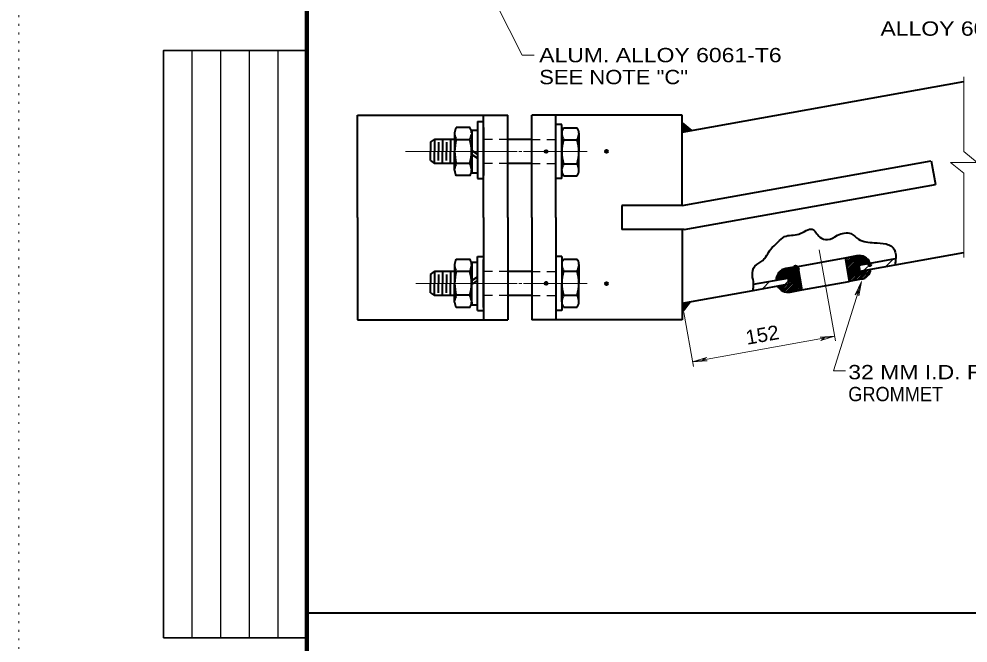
# Model space of a CAD drawing. Extents: x 312583 to 312854, y 144419 to 144597.
# Drawn here: x 312601.2 to 312651.6, y 144456.6 to 144489.8 of the extents above; entities that cross this region are included whole.
import ezdxf

# ---------------------------------------------------------------- set-up
doc = ezdxf.new("R2010")
doc.units = 0
doc.header["$LTSCALE"] = 0.3
doc.header["$PDMODE"] = 32
doc.header["$PDSIZE"] = 0.15
doc.linetypes.add('DOTTED', pattern=[1.5, 0.3, -1.2])
doc.linetypes.add('SHORT_DASHED', pattern=[2.7, 1.5, -1.2])
for name, color, linetype, lineweight in [('1', 7, 'Continuous', 40), ('2', 7, 'Continuous', 40), ('62', 7, 'DOTTED', 13)]:
    doc.layers.add(name, color=color, linetype=linetype, lineweight=lineweight)

msp = doc.modelspace()

# ---------------------------------------------------------------- linework, layer by layer
at = {"layer": '1', "lineweight": 13}
for p, q in [((312626.547, 144490.596), (312627.9347, 144487.8743)), ((312627.9347, 144487.8743), (312628.571, 144487.8743)), ((312651.3947, 144486.7166), (312651.3947, 144482.7453)), ((312627.6663, 144482.753), (312621.74, 144482.753)), ((312627.7583, 144482.753), (312627.9117, 144482.753)), ((312628.0113, 144482.753), (312631.3847, 144482.753)), ((312651.3947, 144481.603), (312651.3947, 144477.118)), ((312643.7127, 144477.5166), (312644.579, 144472.679)), ((312646.0893, 144476.4203), (312646.4957, 144476.819)), ((312647.2623, 144476.6273), (312647.6687, 144477.0336)), ((312627.6663, 144475.7226), (312622.2767, 144475.7226)), ((312627.7583, 144475.7226), (312627.9117, 144475.7226)), ((312628.0113, 144475.7226), (312631.3847, 144475.7226)), ((312640.6997, 144475.4543), (312641.0983, 144475.853)), ((312641.8803, 144475.6613), (312642.072, 144475.853)), ((312645.959, 144475.8376), (312645.6312, 144475.1339)), ((312645.959, 144475.8376), (312645.8169, 144475.0732)), ((312645.6312, 144475.1339), (312645.7974, 144475.3364)), ((312645.8169, 144475.0732), (312645.7974, 144475.3364)), ((312636.5213, 144474.1816), (312637.035, 144471.3143)), ((312636.989, 144471.5673), (312644.533, 144472.932)), ((312644.533, 144472.932), (312643.7587, 144472.886)), ((312643.7587, 144472.886), (312644.0193, 144472.84)), ((312644.533, 144472.932), (312643.797, 144472.702)), ((312643.797, 144472.702), (312644.0193, 144472.84)), ((312636.989, 144471.5673), (312637.7327, 144471.7973)), ((312636.989, 144471.5673), (312637.7633, 144471.6133)), ((312637.7327, 144471.7973), (312637.5027, 144471.6593)), ((312637.7633, 144471.6133), (312637.5027, 144471.6593))]:
    msp.add_line(p, q, dxfattribs=at)
at = {"layer": '1', "lineweight": 25}
for p, q in [((312610.4087, 144456.901), (312610.4087, 144488.1192)), ((312611.9315, 144456.901), (312611.9315, 144488.1192)), ((312613.4543, 144456.901), (312613.4543, 144488.1192)), ((312614.9772, 144456.901), (312614.9772, 144488.1192)), ((312636.4293, 144484.2096), (312636.46, 144484.2403)), ((312636.4293, 144484.1253), (312636.506, 144484.202)), ((312636.4293, 144484.041), (312636.552, 144484.1636)), ((312636.4293, 144483.9566), (312636.598, 144484.1253)), ((312636.4293, 144483.8723), (312636.644, 144484.087)), ((312636.4293, 144483.788), (312636.69, 144484.0486)), ((312636.5137, 144483.788), (312636.736, 144484.018)), ((312636.6133, 144483.8033), (312636.782, 144483.9796)), ((312636.713, 144483.8263), (312636.828, 144483.9413)), ((312636.8127, 144483.8416), (312636.874, 144483.903)), ((312636.4293, 144474.3963), (312636.782, 144474.749)), ((312636.4293, 144474.4806), (312636.6823, 144474.7336)), ((312636.4293, 144474.565), (312636.5827, 144474.7106)), ((312636.4293, 144474.6416), (312636.483, 144474.6953)), ((312636.4293, 144474.312), (312636.7743, 144474.657)), ((312636.4293, 144474.2276), (312636.506, 144474.3043))]:
    msp.add_line(p, q, dxfattribs=at)
at = {"layer": '1'}
for p, q in [((312636.4293, 144483.7726), (312651.3947, 144486.4636)), ((312619.1793, 144479.2416), (312619.1793, 144484.6696)), ((312625.8877, 144479.2416), (312625.8877, 144484.6696)), ((312627.168, 144479.2416), (312627.168, 144484.6696)), ((312628.4407, 144479.2416), (312628.4407, 144484.6696)), ((312629.721, 144479.2416), (312629.721, 144484.6696)), ((312636.4293, 144479.878), (312636.4293, 144484.6696)), ((312625.5657, 144484.34), (312625.5657, 144481.304)), ((312625.5657, 144484.34), (312625.8877, 144484.34)), ((312630.043, 144484.179), (312629.721, 144484.179)), ((312630.043, 144481.304), (312630.043, 144484.179)), ((312636.4293, 144484.2633), (312636.9277, 144483.8646)), ((312624.339, 144483.7343), (312624.339, 144482.753)), ((312625.167, 144484.018), (312624.431, 144484.018)), ((312625.2513, 144483.742), (312625.2513, 144483.8876)), ((312625.2513, 144483.8876), (312625.2513, 144481.6183)), ((312625.2513, 144483.8876), (312625.5657, 144483.8876)), ((312625.2513, 144483.742), (312625.2513, 144482.753)), ((312625.8877, 144484.018), (312625.8877, 144481.465)), ((312629.721, 144481.465), (312629.721, 144484.018)), ((312630.043, 144483.7266), (312630.043, 144482.7453)), ((312630.1273, 144484.0103), (312630.8557, 144484.0103)), ((312630.9477, 144483.7266), (312630.9477, 144482.7376)), ((312623.0587, 144483.2436), (312623.0587, 144482.7453)), ((312624.339, 144483.3893), (312623.2733, 144483.3893)), ((312623.488, 144483.2436), (312623.488, 144482.7453)), ((312623.7027, 144483.3893), (312623.7027, 144482.7453)), ((312623.9173, 144483.2436), (312623.9173, 144482.7453)), ((312624.132, 144483.3893), (312624.132, 144482.7453)), ((312625.167, 144483.374), (312624.431, 144483.374)), ((312628.4407, 144483.3893), (312627.168, 144483.3893)), ((312630.1273, 144483.3586), (312630.8557, 144483.3586)), ((312623.0587, 144482.2623), (312623.0587, 144482.7606)), ((312623.488, 144482.2623), (312623.488, 144482.7606)), ((312623.7027, 144482.1166), (312623.7027, 144482.7606)), ((312623.9173, 144482.2623), (312623.9173, 144482.7606)), ((312624.132, 144482.1166), (312624.132, 144482.7606)), ((312624.339, 144481.7486), (312624.339, 144482.7606)), ((312625.2513, 144482.8066), (312625.5657, 144482.5996)), ((312625.2513, 144481.741), (312625.2513, 144482.753)), ((312630.043, 144481.7333), (312630.043, 144482.7453)), ((312630.9477, 144481.7333), (312630.9477, 144482.7453)), ((312624.339, 144482.1166), (312623.2733, 144482.1166)), ((312625.2513, 144482.592), (312625.5657, 144482.385)), ((312628.4407, 144482.1166), (312627.168, 144482.1166)), ((312636.4293, 144479.878), (312649.6697, 144482.2546)), ((312649.6697, 144482.2546), (312649.8997, 144480.9973)), ((312625.1593, 144482.1013), (312624.431, 144482.1013)), ((312625.2513, 144481.6183), (312625.2513, 144481.741)), ((312625.2513, 144481.6183), (312625.5657, 144481.6183)), ((312630.1273, 144482.0936), (312630.8557, 144482.0936)), ((312625.167, 144481.465), (312624.431, 144481.465)), ((312625.5657, 144481.304), (312625.8877, 144481.304)), ((312630.043, 144481.304), (312629.721, 144481.304)), ((312630.1273, 144481.4496), (312630.8557, 144481.4496)), ((312636.5367, 144478.5976), (312649.8997, 144480.9973)), ((312636.4293, 144479.878), (312633.2323, 144479.878)), ((312633.2323, 144479.878), (312633.2323, 144478.5976)), ((312619.1793, 144479.2416), (312619.1793, 144473.806)), ((312625.8877, 144479.2416), (312625.8877, 144473.806)), ((312627.168, 144479.2416), (312627.168, 144473.806)), ((312628.4407, 144479.2416), (312628.4407, 144473.806)), ((312629.721, 144479.2416), (312629.721, 144473.806)), ((312636.5367, 144478.5976), (312633.2323, 144478.5976)), ((312636.4293, 144478.5976), (312636.4293, 144473.806)), ((312625.5657, 144474.2966), (312625.5657, 144477.1716)), ((312625.5657, 144477.1716), (312625.8877, 144477.1716)), ((312630.043, 144477.1716), (312629.721, 144477.1716)), ((312630.043, 144477.1716), (312630.043, 144474.2966)), ((312642.578, 144476.6426), (312645.0927, 144477.095)), ((312645.0927, 144477.095), (312645.7213, 144477.21)), ((312645.0927, 144477.095), (312645.315, 144475.8376)), ((312647.7453, 144476.7193), (312651.3947, 144477.3786)), ((312624.339, 144476.7346), (312624.339, 144475.7226)), ((312625.167, 144477.0106), (312624.431, 144477.0106)), ((312625.2513, 144476.865), (312625.2513, 144476.7346)), ((312625.2513, 144476.865), (312625.5657, 144476.865)), ((312625.2513, 144474.588), (312625.2513, 144476.865)), ((312625.2513, 144476.7346), (312625.2513, 144475.7226)), ((312625.8877, 144474.4576), (312625.8877, 144477.0106)), ((312629.721, 144477.0106), (312629.721, 144474.4576)), ((312630.043, 144476.75), (312630.043, 144475.738)), ((312630.1273, 144477.026), (312630.8557, 144477.026)), ((312630.9477, 144476.7423), (312630.9477, 144475.7303)), ((312642.5703, 144476.6426), (312641.9493, 144476.5276)), ((312642.578, 144476.6426), (312642.8003, 144475.3853)), ((312645.8133, 144476.6963), (312646.4267, 144476.8113)), ((312645.8133, 144476.6963), (312645.867, 144476.382)), ((312645.867, 144476.382), (312647.7453, 144476.7193)), ((312646.4267, 144476.8113), (312647.776, 144477.0566)), ((312623.0587, 144476.2133), (312623.0587, 144475.7226)), ((312624.339, 144476.3666), (312623.2733, 144476.3666)), ((312623.488, 144476.2133), (312623.488, 144475.7226)), ((312623.7027, 144476.3666), (312623.7027, 144475.7226)), ((312623.9173, 144476.2133), (312623.9173, 144475.7226)), ((312624.132, 144476.3666), (312624.132, 144475.7226)), ((312625.1593, 144476.3743), (312624.431, 144476.3743)), ((312625.2513, 144475.8836), (312625.5657, 144476.0906)), ((312628.4407, 144476.3666), (312627.168, 144476.3666)), ((312630.1273, 144476.3896), (312630.8557, 144476.3896)), ((312623.0587, 144475.2396), (312623.0587, 144475.7303)), ((312623.488, 144475.2396), (312623.488, 144475.7303)), ((312623.7027, 144475.0863), (312623.7027, 144475.7303)), ((312623.9173, 144475.2396), (312623.9173, 144475.7303)), ((312624.132, 144475.0863), (312624.132, 144475.7303)), ((312624.339, 144474.7413), (312624.339, 144475.7303)), ((312625.2513, 144475.669), (312625.5657, 144475.8836)), ((312625.2513, 144474.7336), (312625.2513, 144475.7226)), ((312630.043, 144474.749), (312630.043, 144475.738)), ((312630.9477, 144474.7566), (312630.9477, 144475.738)), ((312640.2013, 144475.3623), (312642.095, 144475.7073)), ((312640.232, 144475.6996), (312642.0413, 144476.0216)), ((312642.0413, 144476.0216), (312642.095, 144475.7073)), ((312642.8003, 144475.3853), (312645.315, 144475.8376)), ((312645.9437, 144475.9526), (312645.315, 144475.8376)), ((312624.339, 144475.0863), (312623.2733, 144475.0863)), ((312625.167, 144475.1016), (312624.431, 144475.1016)), ((312628.4407, 144475.0863), (312627.168, 144475.0863)), ((312630.1273, 144475.117), (312630.8557, 144475.117)), ((312636.4293, 144474.6876), (312640.2013, 144475.3623)), ((312642.1717, 144475.278), (312642.8003, 144475.3853)), ((312625.2513, 144474.7336), (312625.2513, 144474.588)), ((312625.2513, 144474.588), (312625.5657, 144474.588)), ((312636.4293, 144474.2046), (312636.8587, 144474.7643)), ((312625.167, 144474.4576), (312624.431, 144474.4576)), ((312625.5657, 144474.2966), (312625.8877, 144474.2966)), ((312630.043, 144474.2966), (312629.721, 144474.2966)), ((312630.1273, 144474.473), (312630.8557, 144474.473))]:
    msp.add_line(p, q, dxfattribs=at)
at = {"layer": '1', "linetype": 'SHORT_DASHED', "lineweight": 25}
for p, q in [((312627.168, 144483.3893), (312625.8877, 144483.3893)), ((312628.4407, 144483.3893), (312629.721, 144483.3893)), ((312627.168, 144482.1166), (312625.8877, 144482.1166)), ((312628.4407, 144482.1166), (312629.721, 144482.1166)), ((312627.168, 144476.3666), (312625.8877, 144476.3666)), ((312628.4407, 144476.3666), (312629.721, 144476.3666)), ((312627.168, 144475.0863), (312625.8877, 144475.0863)), ((312628.4407, 144475.0863), (312629.721, 144475.0863))]:
    msp.add_line(p, q, dxfattribs=at)
at = {"layer": '1', "lineweight": 35}
for p, q in [((312645.1003, 144477.049), (312645.154, 144477.1026)), ((312645.108, 144476.98), (312645.2613, 144477.1256)), ((312645.1233, 144476.9033), (312645.361, 144477.141)), ((312645.1387, 144476.8343), (312645.4607, 144477.1563)), ((312645.1463, 144476.7653), (312645.5603, 144477.1793)), ((312645.1617, 144476.6963), (312645.6677, 144477.1946)), ((312645.177, 144476.6273), (312645.7597, 144477.21)), ((312645.1847, 144476.5583), (312645.844, 144477.2176)), ((312645.2, 144476.4816), (312645.9207, 144477.21)), ((312645.2153, 144476.4126), (312645.9973, 144477.1946)), ((312645.223, 144476.3436), (312646.0587, 144477.1716)), ((312645.2383, 144476.2746), (312646.1123, 144477.1486)), ((312645.2537, 144476.2056), (312646.166, 144477.118)), ((312645.8363, 144476.704), (312646.212, 144477.0796)), ((312641.6043, 144475.945), (312642.2483, 144476.5813)), ((312641.704, 144475.9603), (312642.348, 144476.5966)), ((312641.8113, 144475.9756), (312642.4477, 144476.6196)), ((312641.911, 144475.9986), (312642.5473, 144476.635)), ((312642.0107, 144476.014), (312642.5857, 144476.589)), ((312645.2613, 144476.129), (312645.8133, 144476.681)), ((312645.2767, 144476.06), (312645.8287, 144476.612)), ((312646.1353, 144476.7576), (312646.3423, 144476.9646)), ((312646.235, 144476.773), (312646.373, 144476.911)), ((312646.3423, 144476.796), (312646.4037, 144476.8573)), ((312641.4203, 144475.922), (312642.0413, 144476.543)), ((312641.4357, 144476.0216), (312641.9417, 144476.5276)), ((312641.4663, 144476.1366), (312641.8113, 144476.4816)), ((312641.5047, 144475.922), (312642.141, 144476.566)), ((312641.7577, 144475.347), (312642.647, 144476.2363)), ((312641.8113, 144475.3163), (312642.6547, 144476.1596)), ((312641.8803, 144475.301), (312642.67, 144476.0906)), ((312642.049, 144475.968), (312642.5933, 144476.5123)), ((312642.0643, 144475.899), (312642.6087, 144476.4433)), ((312642.0797, 144475.83), (312642.6163, 144476.3743)), ((312642.0873, 144475.761), (312642.6317, 144476.3053)), ((312645.292, 144475.991), (312645.8363, 144476.543)), ((312645.2997, 144475.922), (312645.8517, 144476.4663)), ((312645.315, 144475.853), (312645.867, 144476.405)), ((312645.407, 144475.8606), (312645.936, 144476.3896)), ((312645.5067, 144475.876), (312646.0433, 144476.4126)), ((312645.6063, 144475.899), (312646.143, 144476.428)), ((312645.7137, 144475.9143), (312646.2427, 144476.4433)), ((312645.8133, 144475.9296), (312646.3423, 144476.4663)), ((312645.913, 144475.9526), (312646.442, 144476.4816)), ((312646.028, 144475.9833), (312646.442, 144476.3896)), ((312646.189, 144476.06), (312646.3653, 144476.2363)), ((312641.5047, 144475.5923), (312641.5123, 144475.6)), ((312641.543, 144475.5463), (312641.612, 144475.6153)), ((312641.5737, 144475.4926), (312641.7193, 144475.6383)), ((312641.612, 144475.4543), (312641.819, 144475.6536)), ((312641.658, 144475.4083), (312641.9187, 144475.6766)), ((312641.704, 144475.3776), (312642.0183, 144475.692)), ((312641.9417, 144475.278), (312642.6853, 144476.0216)), ((312642.0183, 144475.2703), (312642.7007, 144475.9526)), ((312642.095, 144475.2703), (312642.7083, 144475.8836)), ((312642.187, 144475.278), (312642.7237, 144475.8146)), ((312642.2943, 144475.301), (312642.739, 144475.7456)), ((312642.394, 144475.3163), (312642.7467, 144475.669)), ((312642.4937, 144475.3316), (312642.762, 144475.6)), ((312642.5933, 144475.3546), (312642.7773, 144475.531)), ((312642.693, 144475.37), (312642.785, 144475.462)), ((312642.7927, 144475.3853), (312642.8003, 144475.393))]:
    msp.add_line(p, q, dxfattribs=at)
at = {"layer": '1', "lineweight": 158}
msp.add_lwpolyline([(312616.5, 144423.1446), (312616.5, 144585.0846), (312849, 144585.0846)], dxfattribs=at)
at = {"layer": '1', "lineweight": 35}
for points in [[(312616.5, 144456.901), (312608.8858, 144456.901), (312608.8858, 144488.1192), (312616.5, 144488.1192)], [(312645.936, 144476.7193), (312646.258, 144477.049), (312646.2657, 144477.049)], [(312646.0357, 144476.7346), (312646.304, 144477.003), (312646.304, 144477.003)]]:
    msp.add_lwpolyline(points, dxfattribs=at)
at = {"layer": '1'}
for points in [[(312619.1793, 144484.6696), (312625.8877, 144484.6696), (312627.168, 144484.6696)], [(312636.4293, 144484.6696), (312629.721, 144484.6696), (312628.4407, 144484.6696)], [(312623.0587, 144483.2436), (312623.2733, 144483.3893), (312623.2733, 144482.7453)], [(312623.0587, 144482.2623), (312623.2733, 144482.1166), (312623.2733, 144482.7606)], [(312623.0587, 144476.2133), (312623.2733, 144476.3666), (312623.2733, 144475.7226)], [(312623.0587, 144475.2396), (312623.2733, 144475.0863), (312623.2733, 144475.7303)], [(312619.1793, 144473.806), (312625.8877, 144473.806), (312627.168, 144473.806)], [(312636.4293, 144473.806), (312629.721, 144473.806), (312628.4407, 144473.806)]]:
    msp.add_lwpolyline(points, dxfattribs=at)
at = {"layer": '1', "lineweight": 25}
msp.add_lwpolyline([(312636.9123, 144483.857), (312636.92, 144483.8646), (312636.92, 144483.8646)], dxfattribs=at)
at = {"layer": '1', "lineweight": 13}
for points in [[(312651.3947, 144481.603), (312650.6893, 144482.1703), (312652.1, 144482.1703), (312651.3947, 144482.7453)], [(312645.959, 144475.8376), (312644.476, 144471.0797), (312645.1123, 144471.0797)]]:
    msp.add_lwpolyline(points, dxfattribs=at)
at = {"layer": '1'}
for centre, radius, start, end in [((312625.8144, 144483.9759), 1.5067, 191.77014, 203.36365), ((312624.8667, 144483.7218), 0.5262, 145.8703, 178.33743), ((312623.7741, 144483.9759), 1.5067, 336.63635, 348.22986), ((312624.7218, 144483.7218), 0.5262, 1.66257, 34.1297), ((312631.5151, 144483.9631), 1.5067, 191.77014, 203.36365), ((312630.5675, 144483.7091), 0.5262, 145.8703, 178.33743), ((312630.4225, 144483.7091), 0.5262, 1.66257, 34.1297), ((312629.4749, 144483.9631), 1.5067, 336.63635, 348.22986), ((312627.0577, 144482.6745), 2.7192, 164.99798, 178.595), ((312622.5308, 144482.6745), 2.7192, 1.405, 15.00202), ((312632.7584, 144482.6618), 2.7192, 164.99798, 178.595), ((312628.2315, 144482.6618), 2.7192, 1.405, 15.00202), ((312627.0577, 144482.8079), 2.7192, 181.405, 195.00202), ((312622.5308, 144482.8079), 2.7192, 344.99798, 358.595), ((312632.7584, 144482.7951), 2.7192, 181.405, 195.00202), ((312628.2315, 144482.7951), 2.7192, 344.99798, 358.595), ((312625.8144, 144481.5065), 1.5067, 156.63635, 168.22986), ((312624.8667, 144481.7606), 0.5262, 181.66257, 214.1297), ((312623.7741, 144481.5065), 1.5067, 11.77014, 23.36365), ((312624.7218, 144481.7606), 0.5262, 325.8703, 358.33743), ((312631.5151, 144481.4937), 1.5067, 156.63635, 168.22986), ((312630.5675, 144481.7478), 0.5262, 181.66257, 214.1297), ((312629.4749, 144481.4937), 1.5067, 11.77014, 23.36365), ((312630.4225, 144481.7478), 0.5262, 325.8703, 358.33743), ((312645.8337, 144476.5817), 0.6361, 20.92751, 100.40744), ((312625.8144, 144476.9717), 1.5067, 191.77014, 203.36365), ((312624.8667, 144476.7176), 0.5262, 145.8703, 178.33743), ((312623.7741, 144476.9717), 1.5067, 336.63635, 348.22986), ((312624.7218, 144476.7176), 0.5262, 1.66257, 34.1297), ((312631.5151, 144476.9844), 1.5067, 191.77014, 203.36365), ((312630.5675, 144476.7304), 0.5262, 145.8703, 178.33743), ((312630.4225, 144476.7304), 0.5262, 1.66257, 34.1297), ((312629.4749, 144476.9844), 1.5067, 336.63635, 348.22986), ((312627.0577, 144475.6703), 2.7192, 164.99798, 178.595), ((312622.5308, 144475.6703), 2.7192, 1.405, 15.00202), ((312632.7584, 144475.6831), 2.7192, 164.99798, 178.595), ((312628.2315, 144475.6831), 2.7192, 1.405, 15.00202), ((312642.0561, 144475.9016), 0.6361, 99.90643, 179.34108), ((312645.8337, 144476.5817), 0.6361, 279.9552, 351.41104), ((312627.0577, 144475.8036), 2.7192, 181.405, 195.00202), ((312622.5308, 144475.8036), 2.7192, 344.99798, 358.595), ((312632.7584, 144475.8164), 2.7192, 181.405, 195.00202), ((312628.2315, 144475.8164), 2.7192, 344.99798, 358.595), ((312642.0561, 144475.9016), 0.6361, 208.60683, 280.45563), ((312625.8144, 144474.5022), 1.5067, 156.63635, 168.22986), ((312623.7741, 144474.5022), 1.5067, 11.77014, 23.36365), ((312631.5151, 144474.515), 1.5067, 156.63635, 168.22986), ((312629.4749, 144474.515), 1.5067, 11.77014, 23.36365), ((312624.8667, 144474.7563), 0.5262, 181.66257, 214.1297), ((312624.7218, 144474.7563), 0.5262, 325.8703, 358.33743), ((312630.5675, 144474.7691), 0.5262, 181.66257, 214.1297), ((312630.4225, 144474.7691), 0.5262, 325.8703, 358.33743)]:
    msp.add_arc(centre, radius, start, end, dxfattribs=at)
msp.add_spline([(312640.2013, 144475.3623), (312640.232, 144475.7226), (312640.163, 144476.152), (312640.301, 144476.658), (312640.715, 144476.957), (312641.129, 144477.532), (312641.52, 144477.923), (312641.8803, 144478.222), (312642.6393, 144478.36), (312643.3523, 144478.613), (312643.7433, 144478.199), (312644.1573, 144478.061), (312644.6863, 144478.291), (312645.3993, 144478.383), (312645.8057, 144478.084), (312646.6337, 144477.9), (312647.2777, 144477.831), (312647.5537, 144477.716), (312647.7837, 144477.256), (312647.7683, 144476.9263), (312647.7453, 144476.7193)], degree=3, dxfattribs=at)
for p in [(312629.215, 144482.7453), (312632.412, 144482.753), (312642.4477, 144476.6196), (312642.486, 144476.5736), (312642.532, 144476.5353), (312646.4037, 144476.7346), (312642.5703, 144476.4893), (312629.215, 144475.738), (312632.412, 144475.7226)]:
    msp.add_point(p, dxfattribs=at)
at = {"layer": '2'}
msp.add_line((312616.5, 144458.228), (312849, 144458.228), dxfattribs=at)
at = {"layer": '62'}
msp.add_line((312601.2, 144418.5846), (312601.2, 144596.7846), dxfattribs=at)

# ---------------------------------------------------------------- texts
at = {"layer": '1'}
for s, width, p in [('ALLOY 6061-T6', 1.2, (312646.971, 144488.8997)), ('ALUM. ALLOY 6061-T6', 1.2, (312628.8393, 144487.49)), ('SEE NOTE "C"', 1.15, (312628.8393, 144486.3237)), ('32 MM I.D. RUBBER', 1.2, (312645.2597, 144470.6406)), ('GROMMET', 0.95, (312645.2597, 144469.4743))]:
    msp.add_text(s, height=0.76, dxfattribs=dict(at, width=width)).set_placement(p)
at = {"layer": '1', "width": 1.05}
msp.add_text('152', height=0.76, rotation=10.213, dxfattribs=at).set_placement((312639.8823, 144472.4699))

doc.saveas('drawing.dxf')
